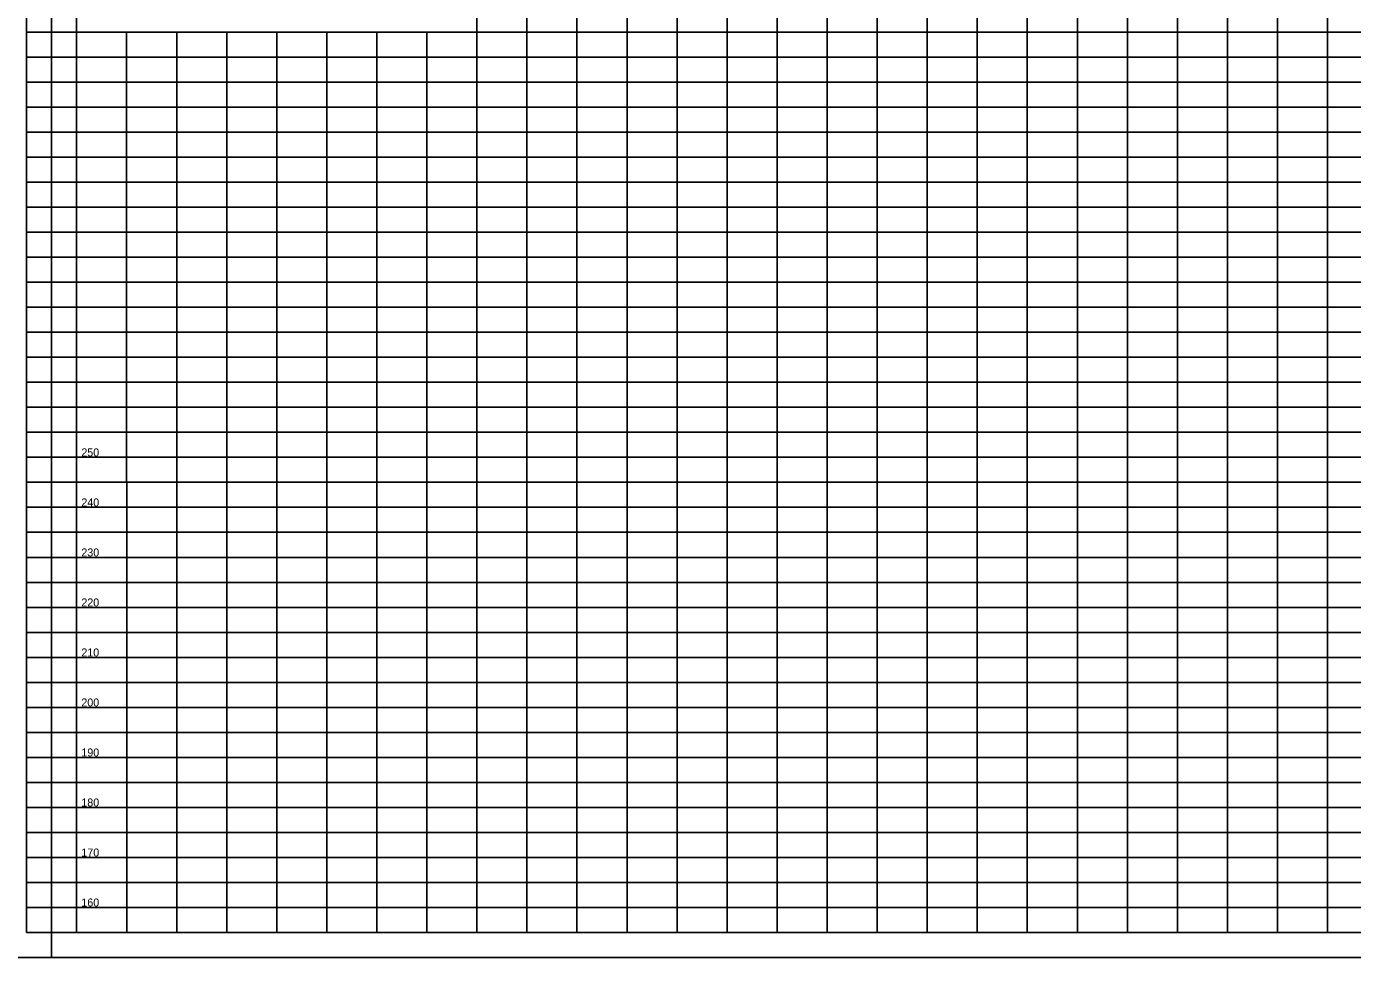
# Model space of a CAD drawing. Extents: x 1914168 to 1925341, y 720939 to 777401.
# Drawn here: x 1919844 to 1921169, y 733439 to 734370 of the extents above; entities that cross this region are included whole.
import ezdxf

# ---------------------------------------------------------------- set-up
doc = ezdxf.new("R2010")
doc.units = 0
for name, color, linetype in [('RD_DDB_ElevTX', 7, 'Continuous'), ('RD_PD_WallFill', 7, 'Continuous'), ('RD_SHT_IplotShp', 7, 'Continuous')]:
    doc.layers.add(name, color=color, linetype=linetype)

msp = doc.modelspace()

# ---------------------------------------------------------------- linework, layer by layer
at = {"layer": 'RD_PD_WallFill'}
for p, q in [((1919844, 733464.2), (1919844, 734514.2)), ((1919894, 733464.2), (1919894.1, 734514.2)), ((1919894, 733464.2), (1919894.1, 734514.2)), ((1920294.1, 733464.2), (1920294, 734514.2)), ((1920294.1, 733464.2), (1920294, 734514.2)), ((1920344.1, 733464.2), (1920344.1, 734514.2)), ((1920344.1, 733464.2), (1920344.1, 734514.2)), ((1920394.1, 733464.2), (1920394.1, 734514.2)), ((1920394.1, 733464.2), (1920394.1, 734514.2)), ((1920444.1, 733464.2), (1920444.1, 734514.2)), ((1920444.1, 733464.2), (1920444.1, 734514.2)), ((1920494.1, 733464.2), (1920494.1, 734514.2)), ((1920494.1, 733464.2), (1920494.1, 734514.2)), ((1920544.1, 733464.2), (1920544.1, 734514.2)), ((1920544.1, 733464.2), (1920544.1, 734514.2)), ((1920594.1, 733464.2), (1920594.1, 734514.2)), ((1920594.1, 733464.2), (1920594.1, 734514.2)), ((1920644.1, 733464.2), (1920644.1, 734514.2)), ((1920644.1, 733464.2), (1920644.1, 734514.2)), ((1920694.1, 733464.2), (1920694.1, 734514.2)), ((1920694.1, 733464.2), (1920694.1, 734514.2)), ((1920744.1, 733464.2), (1920744.1, 734514.2)), ((1920744.1, 733464.2), (1920744.1, 734514.2)), ((1920794.1, 733464.2), (1920794.1, 734514.2)), ((1920794.1, 733464.2), (1920794.1, 734514.2)), ((1920844.1, 733464.2), (1920844.1, 734514.2)), ((1920844.1, 733464.2), (1920844.1, 734514.2)), ((1920894.1, 733464.2), (1920894.1, 734514.2)), ((1920894.1, 733464.2), (1920894.1, 734514.2)), ((1920944.1, 733464.2), (1920944.1, 734514.2)), ((1920944.1, 733464.2), (1920944.1, 734514.2)), ((1920994.1, 733464.2), (1920994.1, 734514.2)), ((1920994.1, 733464.2), (1920994.1, 734514.2)), ((1921044.1, 733464.2), (1921044.1, 734514.2)), ((1921044.1, 733464.2), (1921044.1, 734514.2)), ((1921094.1, 733464.2), (1921094.1, 734514.2)), ((1921094.1, 733464.2), (1921094.1, 734514.2)), ((1921144.1, 733464.2), (1921144.1, 734514.2)), ((1921144.1, 733464.2), (1921144.1, 734514.2)), ((1919844.1, 734364.2), (1925194.1, 734364.2)), ((1919944.1, 733464.2), (1919944, 734364.2)), ((1919944.1, 733464.2), (1919944, 734364.2)), ((1919994.1, 733464.2), (1919994.1, 734364.2)), ((1919994.1, 733464.2), (1919994.1, 734364.2)), ((1920044.1, 733464.2), (1920044.1, 734364.2)), ((1920044.1, 733464.2), (1920044.1, 734364.2)), ((1920094.1, 733464.2), (1920094.1, 734364.2)), ((1920094.1, 733464.2), (1920094.1, 734364.2)), ((1920144.1, 733464.2), (1920144.1, 734364.2)), ((1920144.1, 733464.2), (1920144.1, 734364.2)), ((1920194, 733464.2), (1920194.1, 734364.2)), ((1920194, 733464.2), (1920194.1, 734364.2)), ((1920244, 733464.2), (1920244, 734364.2)), ((1920244, 733464.2), (1920244, 734364.2)), ((1919844.1, 734339.2), (1925194.1, 734339.2)), ((1919844, 734314.2), (1925194.1, 734314.2)), ((1919844.1, 734289.2), (1925194.1, 734289.2)), ((1919844.1, 734264.2), (1925194.1, 734264.2)), ((1919844.1, 734239.2), (1925194.1, 734239.2)), ((1919844.1, 734214.2), (1925194.1, 734214.2)), ((1919844, 734189.2), (1925194.1, 734189.2)), ((1919844, 734164.2), (1925194.1, 734164.2)), ((1919844.1, 734139.2), (1925194.1, 734139.2)), ((1919844.1, 734114.2), (1925194.1, 734114.2)), ((1919844.1, 734089.2), (1925194.1, 734089.2)), ((1919844.1, 734064.2), (1925194.1, 734064.2)), ((1919844, 734039.2), (1925194.1, 734039.2)), ((1919844.1, 734014.2), (1925194.1, 734014.2)), ((1919844.1, 733989.2), (1925194.1, 733989.2)), ((1919844.1, 733964.2), (1925194.1, 733964.2)), ((1919844.1, 733939.2), (1925194.1, 733939.2)), ((1919844, 733914.2), (1925194.1, 733914.2)), ((1919844, 733889.2), (1925194.1, 733889.2)), ((1919844.1, 733864.2), (1925194.1, 733864.2)), ((1919844.1, 733839.2), (1925194.1, 733839.2)), ((1919844.1, 733814.2), (1925194.1, 733814.2)), ((1919844.1, 733789.2), (1925194.1, 733789.2)), ((1919844, 733764.2), (1925194.1, 733764.2)), ((1919844.1, 733739.2), (1925194.1, 733739.2)), ((1919844.1, 733714.2), (1925194.1, 733714.2)), ((1919844.1, 733689.2), (1925194.1, 733689.2)), ((1919844.1, 733664.2), (1925194.1, 733664.2)), ((1919844, 733639.2), (1925194.1, 733639.2)), ((1919844.1, 733614.2), (1925194.1, 733614.2)), ((1919844.1, 733589.2), (1925194.1, 733589.2)), ((1919844.1, 733564.2), (1925194.1, 733564.2)), ((1919844.1, 733539.2), (1925194.1, 733539.2)), ((1919844, 733514.2), (1925194.1, 733514.2)), ((1919844.1, 733489.2), (1925194.1, 733489.2)), ((1919844.1, 733464.2), (1925194.1, 733464.2)), ((1919844.1, 733464.2), (1925194.1, 733464.2))]:
    msp.add_line(p, q, dxfattribs=at)
msp.add_lwpolyline([(1919894.1, 734514.2), (1920294, 734514.2), (1920294, 734364.2), (1919894.1, 734364.2)], close=True, dxfattribs=at)
msp.add_lwpolyline([(1919894.1, 734514.2), (1920294, 734514.2), (1920294, 734364.2), (1919894.1, 734364.2)], close=True, dxfattribs=at)
msp.add_lwpolyline([(1919894.1, 734514.2), (1920294, 734514.2), (1920294, 734364.2), (1919894.1, 734364.2)], close=True, dxfattribs=at)
msp.add_lwpolyline([(1919894.1, 734514.2), (1920294, 734514.2), (1920294, 734364.2), (1919894.1, 734364.2)], close=True, dxfattribs=at)
at = {"layer": 'RD_SHT_IplotShp'}
for points in [[(1914469, 733439.1), (1919869, 733439.1), (1919869, 734539.1), (1914469, 734539.1)], [(1919817.2, 733439.1), (1921567.2, 733439.1), (1921567.2, 734539.1), (1919817.2, 734539.1)]]:
    msp.add_lwpolyline(points, close=True, dxfattribs=at)

# ---------------------------------------------------------------- texts
at = {"layer": 'RD_DDB_ElevTX'}
for s, p in [('250', (1919898.8, 733940.1)), ('240', (1919898.8, 733890.1)), ('230', (1919898.8, 733840.1)), ('220', (1919898.8, 733790.1)), ('210', (1919898.8, 733740.1)), ('200', (1919898.8, 733690.1)), ('190', (1919898.8, 733640.1)), ('180', (1919898.8, 733590.1)), ('170', (1919898.8, 733540.1)), ('160', (1919898.8, 733490.1))]:
    msp.add_text(s, height=8, dxfattribs=at).set_placement(p)

doc.saveas('drawing.dxf')
